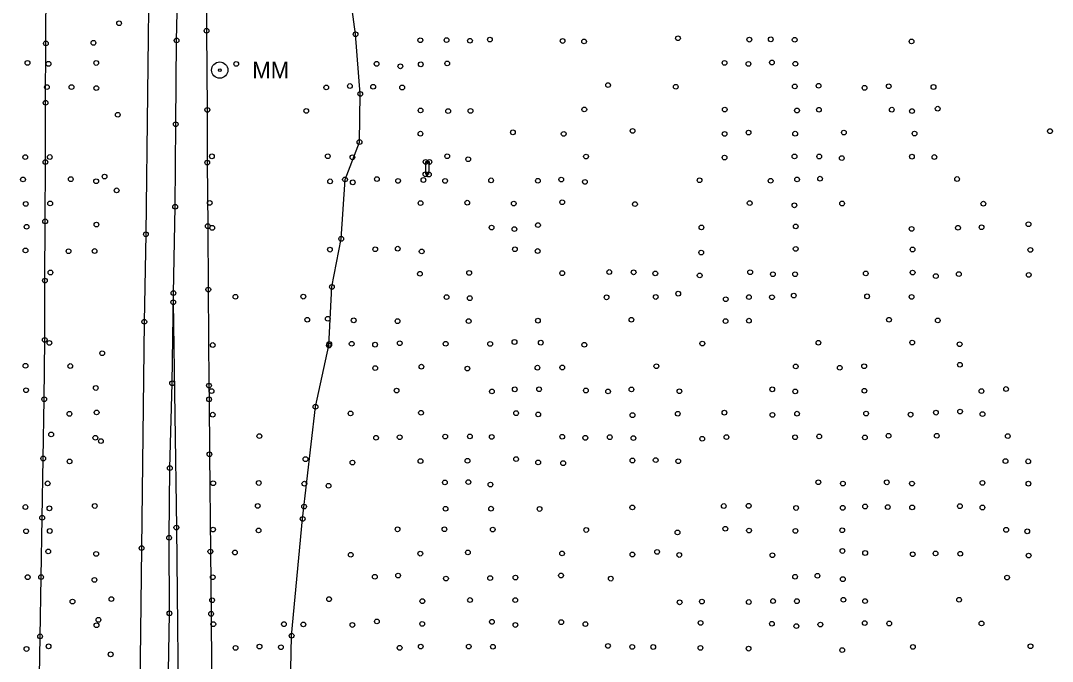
# Model space of a CAD drawing. Extents: x 20503438 to 20508873, y 7964251 to 7984667.
# Drawn here: x 20506685.7 to 20507120.9, y 7972194.6 to 7972464.8 of the extents above; entities that cross this region are included whole.
import ezdxf

# ---------------------------------------------------------------- set-up
doc = ezdxf.new("R2010")
doc.units = 0
for name, color, linetype in [('SurBreakLine', 7, 'Continuous'), ('SurConcreteSlab', 7, 'Continuous'), ('SurDrainageArrowDown', 7, 'Continuous'), ('SurEdgeRoadPaved', 7, 'Continuous'), ('SurMiscStructureLine', 7, 'Continuous'), ('SurPointsNonDTM', 7, 'Continuous'), ('SurRoadPoints', 7, 'Continuous'), ('SurSurveyPoints', 7, 'Continuous')]:
    doc.layers.add(name, color=color, linetype=linetype)

msp = doc.modelspace()

# ---------------------------------------------------------------- linework, layer by layer
at = {"layer": 'SurBreakLine'}
msp.add_lwpolyline([(20506748.06, 7973121.35), (20506742.68, 7972730.78), (20506738.51, 7972374.69), (20506737.86, 7972337.8), (20506736.71, 7972242.37), (20506735.23, 7972125.23), (20506734.95, 7972091.62), (20506733.69, 7971999.07), (20506733.06, 7971941.23), (20506731.39, 7971811.28), (20506730.1, 7971695.4), (20506729.05, 7971627.9), (20506728.3, 7971561.44), (20506726.5, 7971429.38), (20506726.18, 7971406.05), (20506723.05, 7971149.78), (20506722.41, 7971105.59), (20506719.46, 7970853.94), (20506718.67, 7970817.35), (20506718.46, 7970790.57), (20506717.85, 7970756.37), (20506717.5, 7970726.21), (20506716.72, 7970686.1), (20506716.2, 7970609.97)], dxfattribs=at)
at = {"layer": 'SurConcreteSlab'}
msp.add_lwpolyline([(20506750.08, 7972346.05), (20506751.38, 7972251.06), (20506752.37, 7972154.38), (20506752.52, 7972127.89), (20506752.71, 7972092.57), (20506753.04, 7972055.22), (20506753.45, 7972017.94), (20506754.67, 7971931.49)], dxfattribs=at)
at = {"layer": 'SurDrainageArrowDown'}
for points in [[(20506689.2, 7971930.24), (20506689.62, 7971955.24), (20506690.04, 7971980.23), (20506690.47, 7972005.23), (20506690.89, 7972030.22), (20506691.31, 7972055.22), (20506691.73, 7972080.21), (20506692.15, 7972105.21), (20506692.58, 7972130.2), (20506693.01, 7972155.2), (20506693.45, 7972180.19), (20506693.89, 7972205.18), (20506694.33, 7972230.18), (20506694.76, 7972255.17), (20506695.2, 7972280.17), (20506695.64, 7972305.16), (20506695.84, 7972330.16), (20506695.94, 7972355.16), (20506696.03, 7972380.15), (20506696.13, 7972405.15), (20506696.22, 7972430.15), (20506696.32, 7972455.15), (20506696.41, 7972480.15)], [(20506796.03, 7971899.11), (20506797.36, 7971945.99), (20506797.53, 7971992.11), (20506797.66, 7972015.31), (20506797.31, 7972065.83), (20506798.41, 7972115.04), (20506799.16, 7972162.84), (20506800.01, 7972205.46), (20506804.66, 7972254.68), (20506810.08, 7972301.96), (20506815.76, 7972327.8), (20506817, 7972352.49), (20506820.94, 7972372.78), (20506822.53, 7972397.81), (20506828.64, 7972413.59), (20506828.97, 7972433.86), (20506826.98, 7972459.02), (20506824.48, 7972477.91)]]:
    msp.add_lwpolyline(points, dxfattribs=at)
at = {"layer": 'SurEdgeRoadPaved'}
for points in [[(20506739.64, 7971526.5), (20506741.24, 7971640.57), (20506742.69, 7971731.53), (20506743.58, 7971822.14), (20506744.28, 7971871.16), (20506744.63, 7971890.83), (20506745.28, 7971964.75), (20506745.96, 7972013.71), (20506746.36, 7972037.67), (20506746.63, 7972073.65), (20506747.28, 7972111.02), (20506747.6, 7972152.63), (20506747.93, 7972182.29), (20506748.45, 7972214.88), (20506748.32, 7972246.74), (20506748.62, 7972276.12), (20506749.58, 7972311.88), (20506750.14, 7972349.91), (20506750.88, 7972386.32), (20506751.1, 7972421.09), (20506751.49, 7972456.42), (20506752.22, 7972492.22)], [(20506764, 7972481.17), (20506764.12, 7972460.5), (20506764.44, 7972427.13), (20506764.39, 7972404.91), (20506764.62, 7972378.12), (20506764.85, 7972351.4), (20506765.14, 7972310.89), (20506765.18, 7972305.11), (20506765.35, 7972281.94), (20506765.72, 7972240.94), (20506766.04, 7972214.67), (20506766.31, 7972168.31), (20506766.61, 7972139.93), (20506766.7, 7972128.68), (20506766.93, 7972100.59), (20506767.04, 7972084.03), (20506767.28, 7972056.02), (20506767.73, 7972007.15), (20506767.8, 7971998.44), (20506767.87, 7971978.5), (20506767.88, 7971972.82), (20506767.91, 7971961.46), (20506768.35, 7971928.09)]]:
    msp.add_lwpolyline(points, dxfattribs=at)
at = {"layer": 'SurMiscStructureLine'}
msp.add_lwpolyline([(20506857.92, 7972399.9), (20506858.14, 7972405.2), (20506856.52, 7972405.21), (20506856.46, 7972400)], dxfattribs=at)
at = {"layer": 'SurPointsNonDTM'}
for centre in [(20506856.52, 7972405.21), (20506858.14, 7972405.2), (20506856.46, 7972400), (20506857.92, 7972399.9)]:
    msp.add_circle(centre, 1, dxfattribs=at)
at = {"layer": 'SurRoadPoints'}
for radius in [3.43, 0.571]:
    msp.add_circle((20506769.67, 7972443.92), radius, dxfattribs=at)
at = {"layer": 'SurSurveyPoints'}
for centre in [(20506727.22, 7972463.66), (20506764.12, 7972460.5), (20506826.98, 7972459.02), (20506962.99, 7972457.34), (20506696.32, 7972455.15), (20506716.39, 7972455.41), (20506751.49, 7972456.42), (20506854.3, 7972456.52), (20506865.35, 7972456.57), (20506875.24, 7972456.31), (20506883.65, 7972456.78), (20506914.33, 7972456.2), (20506923.38, 7972456.01), (20506993.1, 7972456.76), (20507002.14, 7972456.89), (20507012.23, 7972456.7), (20507061.53, 7972456.01), (20506688.58, 7972446.93), (20506697.43, 7972446.56), (20506717.56, 7972446.92), (20506776.64, 7972446.52), (20506835.85, 7972446.56), (20506845.88, 7972445.52), (20506854.5, 7972446.35), (20506865.66, 7972446.73), (20506982.63, 7972446.95), (20506992.72, 7972446.53), (20507002.63, 7972447.13), (20507012.52, 7972446.58), (20506696.77, 7972436.74), (20506707.14, 7972436.75), (20506717.61, 7972436.35), (20506814.63, 7972436.61), (20506824.59, 7972437.2), (20506834.41, 7972436.91), (20506846.64, 7972436.59), (20506933.5, 7972437.58), (20506962.07, 7972436.9), (20507012.28, 7972437.03), (20507022.32, 7972437.32), (20507041.72, 7972436.45), (20507051.9, 7972437.1), (20507070.79, 7972436.79), (20506828.97, 7972433.86), (20506696.22, 7972430.15), (20506764.44, 7972427.13), (20506806.18, 7972426.7), (20506854.41, 7972426.9), (20506866.05, 7972426.63), (20506875.46, 7972426.71), (20506923.48, 7972427.32), (20506982.71, 7972427.29), (20507013.21, 7972426.89), (20507022.46, 7972427.22), (20507053.18, 7972427.23), (20507061.72, 7972426.65), (20507072.56, 7972427.65), (20506726.66, 7972425.09), (20506751.1, 7972421.09), (20506943.85, 7972418.28), (20507119.94, 7972418.18), (20506828.64, 7972413.59), (20506854.35, 7972417.11), (20506893.34, 7972417.68), (20506914.78, 7972417.02), (20506982.68, 7972417.01), (20506992.77, 7972417.56), (20507012.44, 7972417.11), (20507033, 7972417.58), (20507062.81, 7972417.17), (20506687.64, 7972407.23), (20506696.13, 7972405.15), (20506697.98, 7972407.27), (20506764.39, 7972404.91), (20506766.37, 7972407.56), (20506815.26, 7972407.6), (20506825.66, 7972407.15), (20506865.64, 7972407.6), (20506874.51, 7972406.34), (20506924.2, 7972407.46), (20506982.63, 7972407.04), (20507012.15, 7972407.5), (20507022.58, 7972407.49), (20507032.09, 7972406.8), (20507061.7, 7972407.42), (20507071.15, 7972407.27), (20506686.68, 7972397.82), (20506706.84, 7972397.93), (20506717.55, 7972397.04), (20506721.09, 7972399.02), (20506816.25, 7972397.01), (20506822.53, 7972397.81), (20506825.79, 7972396.6), (20506835.97, 7972397.98), (20506844.9, 7972397.21), (20506855.62, 7972397.58), (20506864.76, 7972397.2), (20506884.17, 7972397.43), (20506903.89, 7972397.26), (20506913.77, 7972397.76), (20506923.74, 7972396.78), (20506972.09, 7972397.46), (20507002.09, 7972397.27), (20507013.24, 7972397.81), (20507022.94, 7972398.13), (20507080.77, 7972398), (20506726.18, 7972393.22), (20506687.85, 7972387.49), (20506698.14, 7972387.7), (20506765.46, 7972387.91), (20506854.41, 7972387.83), (20506874.11, 7972388.02), (20506893.7, 7972387.66), (20506914.17, 7972388.22), (20506944.86, 7972387.43), (20506993.25, 7972387.85), (20507032.23, 7972387.67), (20507091.83, 7972387.6), (20506750.88, 7972386.32), (20507012.11, 7972386.91), (20506696.03, 7972380.15), (20506717.65, 7972378.77), (20507110.87, 7972378.95), (20506688.2, 7972377.87), (20506738.51, 7972374.69), (20506764.62, 7972378.12), (20506766.49, 7972377.41), (20506884.38, 7972377.53), (20506893.99, 7972376.87), (20506903.93, 7972378.57), (20506972.91, 7972377.6), (20507012.67, 7972378.03), (20507061.56, 7972376.98), (20507081.13, 7972377.43), (20507091.07, 7972377.65), (20506820.94, 7972372.78), (20506687.74, 7972367.87), (20506705.91, 7972367.56), (20506716.89, 7972367.64), (20506816.17, 7972368.22), (20506835.26, 7972368.37), (20506844.76, 7972368.62), (20506854.87, 7972367.46), (20506894.18, 7972368.37), (20506903.8, 7972367.64), (20506972.8, 7972366.99), (20507012.65, 7972368.53), (20507061.95, 7972368.28), (20507111.65, 7972368.13), (20506698.25, 7972358.59), (20506854.13, 7972358.06), (20506874.91, 7972358.39), (20506914.16, 7972358.31), (20506934.01, 7972358.79), (20506944.29, 7972358.67), (20506953.43, 7972358.21), (20506972.15, 7972357.35), (20506993.45, 7972358.7), (20507003.05, 7972357.86), (20507012.4, 7972357.85), (20507042.21, 7972358.19), (20507062, 7972358.55), (20507071.78, 7972357.05), (20507081.48, 7972357.9), (20507110.97, 7972357.57), (20506695.94, 7972355.16), (20506750.14, 7972349.91), (20506764.85, 7972351.4), (20506776.29, 7972348.35), (20506804.94, 7972348.41), (20506817, 7972352.49), (20506865.37, 7972348.2), (20506953.61, 7972348.27), (20506963.09, 7972349.66), (20506992.93, 7972348.21), (20507011.86, 7972348.84), (20507042.78, 7972348.54), (20507061.55, 7972348.3), (20506750.08, 7972346.05), (20506875.16, 7972347.76), (20506932.86, 7972348.13), (20506983.13, 7972347.31), (20507002.65, 7972348.16), (20506737.86, 7972337.8), (20506806.61, 7972338.68), (20506815.27, 7972339.06), (20506826.19, 7972338.42), (20506844.68, 7972338.06), (20506874.69, 7972338.09), (20506903.92, 7972338.28), (20506943.34, 7972338.68), (20506983.06, 7972338.09), (20506992.94, 7972338.27), (20507052.02, 7972338.67), (20507072.59, 7972338.38), (20506695.84, 7972330.16), (20506697.81, 7972328.89), (20506766.72, 7972328.01), (20506815.76, 7972327.8), (20506815.89, 7972328.44), (20506825.34, 7972328.53), (20506835.22, 7972328.16), (20506845.6, 7972328.77), (20506864.99, 7972328.54), (20506883.76, 7972328.48), (20506894.03, 7972329.28), (20506905.13, 7972329), (20506923.49, 7972328.12), (20506973.27, 7972328.64), (20507022.24, 7972328.97), (20507061.82, 7972329.04), (20507081.82, 7972328.34), (20506720.1, 7972324.56), (20506687.73, 7972319.27), (20506706.63, 7972319.15), (20506835.28, 7972318.26), (20506854.74, 7972318.87), (20506874.15, 7972318.06), (20506903.7, 7972318.45), (20506914.18, 7972318.53), (20506953.88, 7972319.08), (20507012.67, 7972318.97), (20507031.24, 7972318.42), (20507041.54, 7972319.05), (20507081.92, 7972319.7), (20506717.39, 7972309.9), (20506749.58, 7972311.88), (20506765.14, 7972310.89), (20506894.15, 7972309.33), (20506904.4, 7972309.35), (20506943.37, 7972309.27), (20507002.77, 7972309.33), (20507101.41, 7972309.46), (20506687.97, 7972308.94), (20506695.64, 7972305.16), (20506765.18, 7972305.11), (20506766.22, 7972308.6), (20506844.3, 7972308.79), (20506884.51, 7972308.45), (20506924.15, 7972308.84), (20506933.49, 7972308.44), (20506963.59, 7972308.51), (20507012.47, 7972308.46), (20507041.63, 7972308.74), (20507091.03, 7972308.58), (20506810.08, 7972301.96), (20506706.26, 7972299), (20506717.75, 7972299.58), (20506766.72, 7972298.63), (20506824.87, 7972299.16), (20506854.59, 7972299.45), (20506894.72, 7972299.27), (20506904.04, 7972298.76), (20506943.81, 7972298.43), (20506962.92, 7972299.04), (20506982.57, 7972299.49), (20507002.84, 7972298.56), (20507013.24, 7972299.06), (20507042.35, 7972299.11), (20507061.13, 7972298.66), (20507071.82, 7972299.5), (20507082, 7972299.97), (20507091.46, 7972298.87), (20506698.56, 7972290.32), (20506717.2, 7972288.91), (20506719.54, 7972287.52), (20506786.39, 7972289.6), (20506835.62, 7972288.9), (20506845.59, 7972289.13), (20506864.8, 7972289.41), (20506875.22, 7972289.48), (20506884.42, 7972289.26), (20506914.16, 7972289.34), (20506923.91, 7972288.88), (20506934.22, 7972289.16), (20506944.18, 7972288.76), (20506973.21, 7972288.47), (20506983.45, 7972289.18), (20507012.4, 7972289.12), (20507022.59, 7972289.47), (20507041.85, 7972289.04), (20507051.84, 7972289.74), (20507072.17, 7972289.75), (20507102.14, 7972289.61), (20506695.2, 7972280.17), (20506706.31, 7972278.95), (20506765.35, 7972281.94), (20506805.86, 7972279.89), (20506854.38, 7972279.09), (20506874.2, 7972279.21), (20506894.7, 7972279.91), (20506943.78, 7972279.32), (20506953.59, 7972279.47), (20506963.12, 7972279.03), (20507101.17, 7972279.09), (20507110.76, 7972278.96), (20506748.62, 7972276.12), (20506825.66, 7972278.44), (20506904.02, 7972278.49), (20506914.56, 7972278.2), (20506786.14, 7972269.85), (20506864.66, 7972270.08), (20506874.56, 7972270.2), (20507022.21, 7972270.14), (20507051.09, 7972270.13), (20507091.44, 7972269.89), (20506697.07, 7972269.68), (20506766.9, 7972269.73), (20506805.38, 7972269.54), (20506815.57, 7972268.65), (20506883.89, 7972269.19), (20507032.58, 7972269.61), (20507061.71, 7972269.59), (20507110.82, 7972269.55), (20506687.72, 7972259.71), (20506697.81, 7972259.15), (20506716.97, 7972260.15), (20506785.7, 7972260.16), (20506805.26, 7972259.9), (20506864.93, 7972258.99), (20506884.14, 7972259), (20506904.6, 7972258.88), (20506943.74, 7972259.53), (20506982.31, 7972260.13), (20506992.82, 7972260.21), (20507012.83, 7972259.31), (20507032.5, 7972259.37), (20507041.93, 7972259.93), (20507051.51, 7972259.69), (20507061.79, 7972259.55), (20507081.94, 7972260.06), (20507091.44, 7972259.51), (20506694.76, 7972255.17), (20506804.66, 7972254.68), (20506688, 7972249.51), (20506697.98, 7972249.6), (20506751.38, 7972251.06), (20506766.86, 7972250.18), (20506786.07, 7972249.82), (20506844.68, 7972250.31), (20506864.48, 7972250.32), (20506884.84, 7972250.2), (20506924.3, 7972250.03), (20506962.8, 7972248.99), (20506982.97, 7972250.56), (20506992.97, 7972249.78), (20507012.56, 7972249.63), (20507032.29, 7972249.91), (20507101.45, 7972250.09), (20507110.35, 7972249.46), (20506748.32, 7972246.74), (20506697.34, 7972240.98), (20506717.55, 7972239.96), (20506736.71, 7972242.37), (20506765.72, 7972240.94), (20506776.09, 7972240.54), (20506824.94, 7972239.57), (20506854.29, 7972240.05), (20506874.36, 7972240.56), (20506914.1, 7972240.12), (20506943.77, 7972239.69), (20506954.18, 7972240.8), (20506963.54, 7972239.49), (20507002.82, 7972239.38), (20507032.37, 7972241.17), (20507041.96, 7972240.32), (20507062.03, 7972239.78), (20507071.67, 7972240.13), (20507082.09, 7972240.02), (20507110.93, 7972239.22), (20506844.94, 7972230.82), (20506913.66, 7972230.83), (20507021.83, 7972230.71), (20506688.65, 7972230.13), (20506694.33, 7972230.18), (20506716.82, 7972228.99), (20506766.72, 7972230.11), (20506835.1, 7972230.29), (20506865.12, 7972229.55), (20506883.76, 7972229.73), (20506894.42, 7972229.96), (20506934.64, 7972229.51), (20507012.4, 7972230.32), (20507032.54, 7972229.29), (20507101.83, 7972229.97), (20506707.56, 7972219.86), (20506723.95, 7972220.9), (20506766.46, 7972220.42), (20506815.79, 7972220.85), (20506855.16, 7972220.01), (20506875.27, 7972220.5), (20506894.36, 7972220.45), (20506963.7, 7972219.53), (20506973.07, 7972219.86), (20506992.86, 7972219.65), (20507003.11, 7972220.07), (20507013.17, 7972220.02), (20507032.78, 7972220.59), (20507041.92, 7972220.05), (20507081.61, 7972220.61), (20506748.45, 7972214.88), (20506766.04, 7972214.67), (20506717.69, 7972209.85), (20506718.52, 7972212.15), (20506766.97, 7972210.32), (20506796.76, 7972210.31), (20506804.95, 7972210.22), (20506825.63, 7972209.97), (20506835.96, 7972211.46), (20506855.11, 7972210.43), (20506884.51, 7972211.3), (20506894.41, 7972209.98), (20506913.73, 7972211.16), (20506923.97, 7972210.37), (20506972.55, 7972210.87), (20507002.6, 7972210.51), (20507012.94, 7972209.51), (20507023.06, 7972210.16), (20507041.78, 7972210.78), (20507052.11, 7972210.59), (20507091.05, 7972210.61), (20506693.89, 7972205.18), (20506800.01, 7972205.46), (20506697.48, 7972200.97), (20506776.36, 7972200.32), (20506786.45, 7972200.86), (20506795.49, 7972200.6), (20506845.57, 7972200.34), (20506854.46, 7972200.85), (20506874.72, 7972200.88), (20506884.91, 7972200.81), (20506933.46, 7972201.13), (20506943.7, 7972200.75), (20506952.54, 7972200.69), (20506972.46, 7972200.31), (20507062.11, 7972200.72), (20507111.72, 7972200.99), (20506688.16, 7972199.86), (20506723.66, 7972197.6), (20506992.79, 7972200), (20507032.28, 7972199.38)]:
    msp.add_circle(centre, 1, dxfattribs=at)

# ---------------------------------------------------------------- texts
at = {"layer": 'SurRoadPoints'}
msp.add_text('MM', height=6.995, rotation=360, dxfattribs=at).set_placement((20506783.38, 7972440.43))

doc.saveas('drawing.dxf')
